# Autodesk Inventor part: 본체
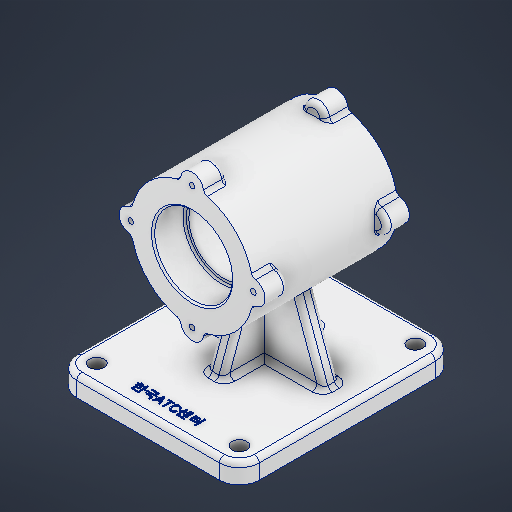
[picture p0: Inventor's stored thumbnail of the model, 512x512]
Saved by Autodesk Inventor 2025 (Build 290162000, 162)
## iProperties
Created: 2025-08
Part Number: 본체
Material: 알루미늄 6061
Document SubType Name: Modeling
Designer: infra005
Density: 2.7 g/cm^3
Appearance: 알루미늄 - 평지
Mass: 1221.05 g
Surface Area: 808.903 cm^2
Volume: 452.242 cm^3
Author: infra005
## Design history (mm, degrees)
sketch "스케치1"
  geometry: L1 (55, 65)-(-55, 65); L2 (-55, 65)-(-55, -65); L3 (-55, -65)-(55, -65); L4 (55, -65)-(55, 65); L5 (55, 65)-(-55, -65); L6 (-55, 65)-(55, -65); 1 further point
  constraints: 12 end point, 2 midpoint, 2 parallel, 1 horizontal, 1 perpendicular
  dimensions: "d0" = 110 distance of L3.end L2.end; "d1" = 130 distance of L2.end L1.end
extrude "돌출1" new body sketch "스케치1" distance "d2" = 12; taper "d3" = 0 deg
sketch "스케치2"
  geometry: L1 (-55, -65)-(55, -65) reference; L2 (-55, 65)-(-55, -65) reference; L3 (0, 0)-(-113.867, 0); L4 (0, 0)-(0, 97.396); L5 (0, 0)-(113.867, 0); L6 (55, 65)-(-55, 65) reference; L7 (55, -65)-(55, 65) reference; L8 (55, 65)-(-55, 65) reference; L9 (-55, 65)-(-55, -65) reference; L10 (-55, -65)-(55, -65) reference; C1 r 4.5 at (-43, -53); C2 r 4.5 at (-43, 53); C3 r 4.5 at (43, -53); C4 r 4.5 at (43, 53)
  constraints: 6 end point, 4 centre point, 4 symmetric about line, 1 horizontal, 1 vertical, 3 other
  dimensions: "d4" = 9 diameter of C1; "d8" = 12 distance from line of L6 C2.centre; "d9" = 86 distance of C2.centre C4.centre
extrude "돌출2" cut sketch "스케치2" extent not by distance; stored distance "d10" = 0; taper "d11" = 0 deg
sketch "스케치3"
  geometry: L1 (0, -65)-(0, 65) reference; L2 (105.5, 38.5)-(105.5, 19.5); L3 (105.5, 38.5)-(119, 38.5); L4 (119, 38.5)-(119, -48.5); L5 (119, -48.5)-(105.5, -48.5); L6 (105.5, -48.5)-(105.5, -29.5); L7 (105.5, -29.5)-(82, -29.5); L8 (82, -29.5)-(82, 19.5); L9 (82, 19.5)-(105.5, 19.5); L10 (119, -5)-(82, -5); L11 (0, 65)-(12, 65) reference; 1 further point
  constraints: 18 end point, 5 perpendicular, 2 midpoint, 2 vertical
  dimensions: "d17" = 19 distance of L2.start L2.end; "d18" = 13.5 distance of L2.start L3.end; "d19" = 87 distance of L3.end L4.end; "d20" = 19 distance of L5.end L6.end; "d21" = 70 distance between parallel lines of L10 L11; "d22" = 82 distance between parallel lines of L1 L8; "d23" = 23.5 distance of L8.end L2.end; "d24" = 13.5 distance between parallel lines of L4 L6
revolve "회전1" sketch "스케치3" stored, may be unused: angle "d25" = 90 deg
sketch "스케치4"
  geometry: C1 r 23.5 at (0, 0) reference; C2 r 21 at (0, 0); 1 further point
  constraints: 1 centre point, 1 coincident
  dimensions: "d26" = 42 diameter of C2
extrude "돌출3" cut sketch "스케치4" extent not by distance; stored distance "d27" = 0; taper "d28" = 0 deg
sketch "스케치5"
  geometry: L1 (0, 0)-(0, 72.178); L2 (0, 0)-(-65.912, 0); C1 r 7 at (0, 37); C2 r 7 at (-37, 0); C3 r 7 at (0, -37); C4 r 7 at (37, 0); 1 further point
  constraints: 4 centre point, 4 end point, 1 horizontal, 1 point on line, 1 vertical, 1 vertical alignment, 10 other
  dimensions: "d29" = 14 diameter of C1; "d32" = 360 deg dimension on L1.start C1.centre (derived)
extrude "돌출4" join sketch "스케치5" distance "d34" = 14; taper "d35" = 0 deg
sketch "스케치6"
  geometry: A1 r 7 centre (0, 37) between (6.969, 36.338) and (-6.969, 36.338) reference; A2 r 7 centre (-37, 0) between (-36.338, 6.969) and (-36.338, -6.969) reference; A3 r 7 centre (37, 0) between (36.338, -6.969) and (36.338, 6.969) reference; A4 r 7 centre (0, -37) between (-6.969, -36.338) and (6.969, -36.338) reference; 2 further points
  constraints: 1 other
extrude "돌출5" join sketch "스케치6" distance "d36" = 14; taper "d37" = 0 deg
node "작업 평면1"
sketch "스케치8"
  geometry: L1 (0, 12)-(110, 12) reference; L2 (14, 12)-(29.664, 55.036); L3 (0, 0)-(0, 12) reference; L4 (55, 82)-(55, 0); L5 (96, 12)-(80.336, 55.036); L6 (29.664, 55.036)-(80.336, 55.036); A1 r 37 centre (55, 82) between (18.662, 75.031) and (48.031, 45.662) reference; A2 r 37 centre (55, 82) between (61.969, 45.662) and (91.338, 75.031) reference; 1 further point
  constraints: 8 end point, 2 symmetric about line, 1 horizontal, 1 point on circle, 1 point on line, 1 vertical
  dimensions: "d40" = 110 deg angle of L1 L2; "d41" = 14 distance from line of L2.start L3
extrude "돌출6" join sketch "스케치8" stored distance "d42" = 10; taper "d43" = 0 deg
sketch "스케치9"
  geometry: L1 (12, -65)-(12, 65) reference; L2 (12, -35)-(45, -22.989); L3 (45, -34.5)-(45, 24.5) reference; L4 (45, 12.989)-(12, 25); L5 (119, -34.5)-(119, 24.5) reference; L6 (119, -5)-(-33.779, -5); 1 further point
  constraints: 6 end point, 4 point on line, 1 midpoint, 1 other
  dimensions: "d44" = 60 distance of L4.end L2.start; "d45" = 110 deg angle of L1 L2; "d46" = 110 deg angle of L1 L4
extrude "돌출7" join sketch "스케치9" stored distance "d47" = 10; taper "d48" = 0 deg
sketch "스케치10"
  geometry: L1 (0, 0)-(-5, 0) reference; A1 r 7 centre (0, 74) between (6.969, 73.338) and (-6.969, 73.338) reference; A2 r 7 centre (-37, 37) between (-36.338, 43.969) and (-36.338, 30.031) reference; A3 r 7 centre (0, 0) between (-6.969, 0.662) and (6.969, 0.662) reference; A4 r 7 centre (37, 37) between (36.338, 30.031) and (36.338, 43.969) reference; 5 further points
  constraints: 4 coincident
hole "구멍1" sketch "스케치10" at (0, 74), (-37, 37), (0, 0), (37, 37) diameter "d49" = 3.242; stored, may be unused: countersink angle "d53" = 90 deg, drill point angle "d55" = 118 deg; dims "d50" = 8, "d51" = 4, "d52" = 2, "d54" = 10
sketch "스케치11"
  geometry: C1 r 1.621 at (37, -37) reference; A1 r 7 centre (0, 0) between (6.969, -0.662) and (-6.969, -0.662) reference; A2 r 7 centre (-37, -37) between (-36.338, -30.031) and (-36.338, -43.969) reference; A3 r 7 centre (0, -74) between (-6.969, -73.338) and (6.969, -73.338) reference; A4 r 7 centre (37, -37) between (36.338, -43.969) and (36.338, -30.031) reference; 5 further points
  constraints: 4 coincident
hole "구멍2" sketch "스케치11" at (-37, -37), (0, 0), (37, -37), (0, -74) diameter "d56" = 3.242; stored, may be unused: countersink angle "d60" = 90 deg, drill point angle "d62" = 118 deg; dims "d57" = 8, "d58" = 4, "d59" = 2, "d61" = 10
fillet "모깎기1" dims "d63" = 12
fillet "모깎기2" dims "d64" = 1
fillet "모깎기3" dims "d65" = 3
fillet "모깎기4" dims "d66" = 3
node "작업 평면2"
sketch "스케치13"
  geometry: L1 (-20.838, -48.015)-(20.838, -48.015); L2 (20.838, -48.015)-(20.838, -57.985); L3 (20.838, -57.985)-(-20.838, -57.985); L4 (-20.838, -57.985)-(-20.838, -48.015); L5 (-20.838, -53)-(20.838, -53); L6 (0, -48.015)-(0, -57.985); L7 (-43, -65)-(43, -65) reference; L8 (0, -65)-(0, 108.668); L9 (-43.101, 7)-(-43.101, 3) reference; L10 (-43.101, 5)-(43.101, 5); L11 (43.101, 3)-(43.101, 7) reference; 3 further points
  constraints: 9 midpoint, 8 end point, 1 vertical, 1 vertical alignment, 2 other
  dimensions: "d68" = 58 distance from line of point (0, -53) L10
feature "엠보싱1" sketch "스케치13" dims "d0" = 110, "d1" = 130, "d69" = 0.5, "d70" = 0
chamfer "모따기1" distance "d71" = 1; stored, may be unused: second distance "d72" = 2, angle "d73" = 45 deg
chamfer "모따기2" distance "d74" = 1; stored, may be unused: second distance "d75" = 2, angle "d76" = 45 deg
node "솔리드1"
node "투영된 루프1"
node "스케치 - 원형 패턴1" dims "d32" = 360 deg (derived)
feature "A9D066F2-1C7D-4E18-AEED-F7BC21143FA4" dims "d49" = 3.242, "d50" = 8, "d51" = 4, "d52" = 2, "d53" = 90 deg, "d54" = 10, "d55" = 118 deg
other parameters: "d67" = 0.5
